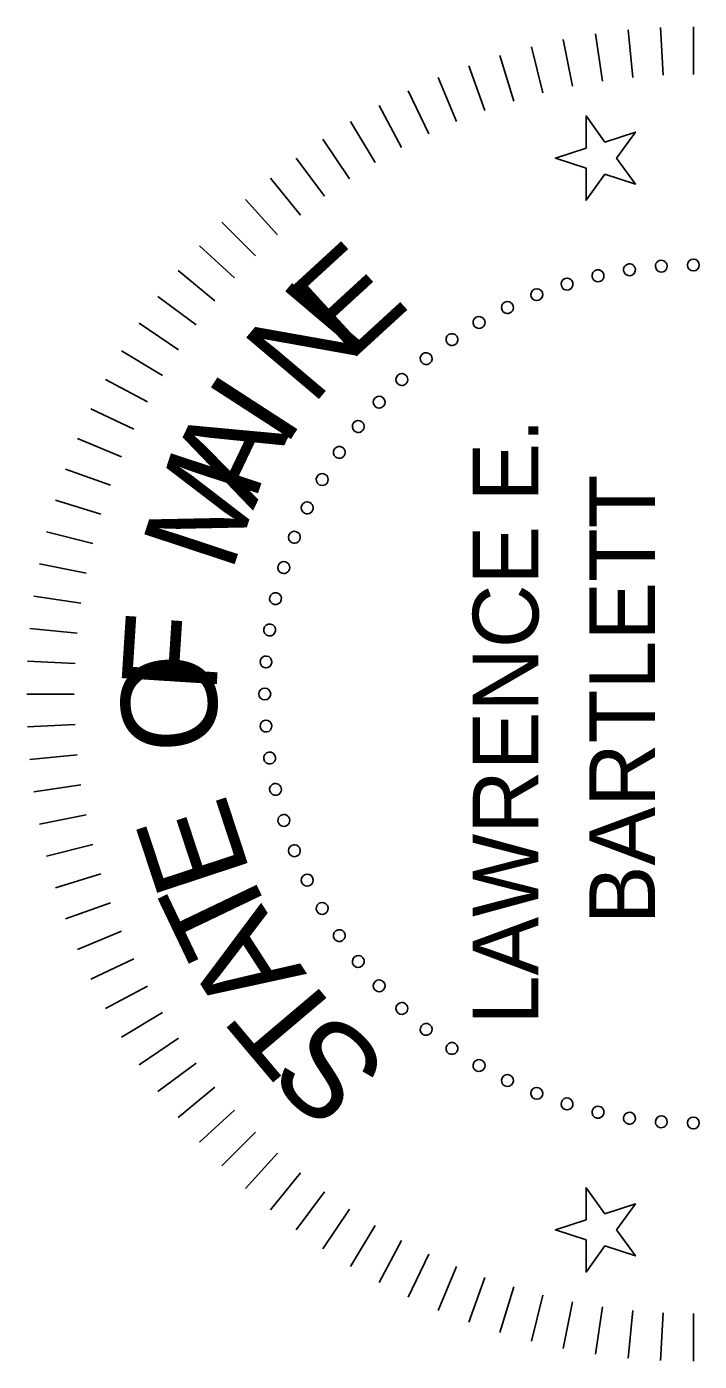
# Model space of a CAD drawing. Extents: x 9916 to 916479, y 6678 to 329942.
# Drawn here: x 916414.06 to 916434.15, y 329765.72 to 329805.54 of the extents above; entities that cross this region are included whole.
import ezdxf

# ---------------------------------------------------------------- set-up
doc = ezdxf.new("R2010")
doc.units = 0
doc.layers.add('Border', color=7, linetype='Continuous')
doc.layers.add('Default', color=7, linetype='Continuous')

# ---------------------------------------------------------------- blocks, each defined once
blk = doc.blocks.new('STAMP')
at = {"layer": 'Default'}
for p, q in [((-0.0007807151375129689, 0.009426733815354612), (-0.0007249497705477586, 0.00886053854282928)), ((-0.00039082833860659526, 0.009455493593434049), (-0.00036291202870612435, 0.008887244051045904)), ((-4.996003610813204e-18, 0.009465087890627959), (-4.996003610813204e-18, 0.008896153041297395)), ((0.0003908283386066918, 0.009455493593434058), (0.0003629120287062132, 0.008887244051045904)), ((0.0007807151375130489, 0.009426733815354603), (0.0007249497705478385, 0.00886053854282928)), ((-0.0015539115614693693, 0.009312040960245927), (-0.0014429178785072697, 0.00875403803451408)), ((-0.0011687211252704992, 0.009378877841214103), (-0.0010852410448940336, 0.008816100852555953)), ((0.0011687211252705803, 0.009378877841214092), (0.0010852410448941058, 0.008816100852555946)), ((0.001553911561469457, 0.009312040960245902), (0.001442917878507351, 0.008754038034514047)), ((-0.002312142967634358, 0.009122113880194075), (-0.002146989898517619, 0.008577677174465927)), ((-0.0019353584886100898, 0.009226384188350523), (-0.0017971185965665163, 0.008674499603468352)), ((0.0019353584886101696, 0.009226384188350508), (0.0017971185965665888, 0.008674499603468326)), ((0.0023121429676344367, 0.00912211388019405), (0.0021469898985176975, 0.008577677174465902)), ((-0.0026833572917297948, 0.008999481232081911), (-0.0024916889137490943, 0.00846380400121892)), ((0.002683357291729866, 0.008999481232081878), (0.0024916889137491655, 0.008463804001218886)), ((-0.003048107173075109, 0.008858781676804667), (-0.0028303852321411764, 0.008333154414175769)), ((0.00304810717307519, 0.008858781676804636), (0.002830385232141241, 0.008333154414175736)), ((-0.003405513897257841, 0.008700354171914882), (-0.0031622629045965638, 0.008186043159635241)), ((0.0034055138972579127, 0.008700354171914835), (0.0031622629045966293, 0.008186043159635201)), ((-0.0037547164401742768, 0.008524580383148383), (-0.0034865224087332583, 0.00802282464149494)), ((0.003754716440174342, 0.008524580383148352), (0.0034865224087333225, 0.008022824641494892)), ((-0.004094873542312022, 0.008331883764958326), (-0.003802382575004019, 0.0078438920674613)), ((0.0040948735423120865, 0.008331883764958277), (0.0038023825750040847, 0.007843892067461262)), ((-0.004425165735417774, 0.008122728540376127), (-0.004109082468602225, 0.0076496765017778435)), ((0.004425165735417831, 0.008122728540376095), (0.004109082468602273, 0.007649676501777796)), ((-0.004744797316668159, 0.007897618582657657), (-0.004405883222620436, 0.007440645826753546)), ((0.004744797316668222, 0.007897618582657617), (0.004405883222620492, 0.007440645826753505)), ((-0.0050529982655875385, 0.0076570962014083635), (-0.004692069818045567, 0.007217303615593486)), ((0.005052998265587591, 0.0076570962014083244), (0.004692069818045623, 0.0072173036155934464)), ((-0.005349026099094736, 0.007401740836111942), (-0.004966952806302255, 0.006980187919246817)), ((0.0053490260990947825, 0.0074017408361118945), (0.004966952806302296, 0.00698018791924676)), ((-0.0056321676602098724, 0.00713216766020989), (-0.00522986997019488, 0.006729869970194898)), ((0.005632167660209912, 0.007132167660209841), (0.005229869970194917, 0.006729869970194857)), ((-0.005901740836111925, 0.006849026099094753), (-0.005480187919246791, 0.006466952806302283)), ((0.005901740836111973, 0.0068490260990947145), (0.00548018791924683, 0.006466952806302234)), ((-0.006157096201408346, 0.006552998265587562), (-0.005717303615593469, 0.006192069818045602)), ((0.006157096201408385, 0.006552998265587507), (0.005717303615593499, 0.006192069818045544)), ((-0.00639761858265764, 0.006244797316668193), (-0.0059406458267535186, 0.0059058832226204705)), ((0.006397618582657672, 0.006244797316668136), (0.00594064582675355, 0.005905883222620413)), ((-0.006622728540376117, 0.0059251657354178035), (-0.006149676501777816, 0.005609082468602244)), ((0.006622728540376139, 0.005925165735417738), (0.006149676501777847, 0.005609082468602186)), ((-0.006831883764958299, 0.005594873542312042), (-0.0063438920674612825, 0.0053023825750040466)), ((0.006831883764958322, 0.005594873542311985), (0.006343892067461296, 0.005302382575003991)), ((-0.007024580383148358, 0.005254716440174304), (-0.006522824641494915, 0.004986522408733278)), ((0.007024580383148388, 0.005254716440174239), (0.006522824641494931, 0.004986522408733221)), ((-0.007200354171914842, 0.00490551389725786), (-0.006686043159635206, 0.004662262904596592)), ((0.00720035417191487, 0.004905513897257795), (0.00668604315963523, 0.004662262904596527)), ((-0.0073587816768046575, 0.004548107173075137), (-0.006833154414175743, 0.004330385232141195)), ((0.0073587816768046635, 0.0045481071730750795), (0.006833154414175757, 0.0043303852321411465)), ((-0.007499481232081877, 0.004183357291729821), (-0.006963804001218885, 0.003991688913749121)), ((0.0074994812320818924, 0.004183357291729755), (0.006963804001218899, 0.003991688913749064)), ((-0.007622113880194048, 0.0038121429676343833), (-0.007077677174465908, 0.003646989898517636)), ((0.007622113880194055, 0.003812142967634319), (0.007077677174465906, 0.00364698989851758)), ((-0.007726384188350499, 0.0034353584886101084), (-0.007174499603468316, 0.003297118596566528)), ((0.0077263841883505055, 0.0034353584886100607), (0.007174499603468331, 0.003297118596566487)), ((-0.0078120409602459, 0.0030539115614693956), (-0.007254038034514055, 0.0029429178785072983)), ((-0.006396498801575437, 0.0031478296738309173), (-0.006515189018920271, 0.0027825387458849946)), ((-0.006277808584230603, 0.0027825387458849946), (-0.006396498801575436, 0.0031478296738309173)), ((0.006277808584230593, 0.0027825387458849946), (0.006396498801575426, 0.0031478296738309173)), ((0.006396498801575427, 0.0031478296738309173), (0.0065151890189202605, 0.0027825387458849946)), ((0.007812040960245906, 0.003053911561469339), (0.007254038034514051, 0.0029429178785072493)), ((-0.006515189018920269, 0.0027825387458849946), (-0.006899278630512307, 0.0027825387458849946)), ((-0.006899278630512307, 0.0027825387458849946), (-0.006588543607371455, 0.002556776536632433)), ((-0.005893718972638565, 0.0027825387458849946), (-0.006277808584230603, 0.0027825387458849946)), ((-0.006204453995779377, 0.002556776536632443), (-0.005893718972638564, 0.0027825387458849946)), ((0.0062044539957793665, 0.002556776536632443), (0.005893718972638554, 0.0027825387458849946)), ((0.005893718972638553, 0.0027825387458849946), (0.00627780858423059, 0.0027825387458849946)), ((0.00651518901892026, 0.0027825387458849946), (0.006899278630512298, 0.0027825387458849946)), ((0.006899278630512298, 0.0027825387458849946), (0.006588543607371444, 0.002556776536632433)), ((-0.007878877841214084, 0.002668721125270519), (-0.007316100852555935, 0.0025852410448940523)), ((-0.006588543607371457, 0.002556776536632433), (-0.00670723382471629, 0.0021914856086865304)), ((-0.006085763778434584, 0.0021914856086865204), (-0.006204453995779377, 0.002556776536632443)), ((0.006085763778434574, 0.0021914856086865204), (0.006204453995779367, 0.002556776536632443)), ((0.006588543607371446, 0.002556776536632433), (0.0067072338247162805, 0.0021914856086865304)), ((0.007878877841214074, 0.0026687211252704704), (0.007316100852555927, 0.0025852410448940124)), ((-0.006707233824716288, 0.0021914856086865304), (-0.006396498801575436, 0.0024172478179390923)), ((-0.006396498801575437, 0.0024172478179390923), (-0.006085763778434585, 0.0021914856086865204)), ((0.006396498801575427, 0.0024172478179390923), (0.006085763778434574, 0.0021914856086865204)), ((0.006707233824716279, 0.0021914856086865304), (0.006396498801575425, 0.0024172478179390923)), ((-0.007926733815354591, 0.00228071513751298), (-0.007360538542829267, 0.0022249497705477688)), ((0.007926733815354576, 0.0022807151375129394), (0.007360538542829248, 0.002224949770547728)), ((-0.007955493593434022, 0.0018908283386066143), (-0.007387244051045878, 0.0018629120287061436)), ((0.007955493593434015, 0.0018908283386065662), (0.007387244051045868, 0.001862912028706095)), ((-0.007965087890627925, 0.0015000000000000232), (-0.0073961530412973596, 0.0015000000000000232)), ((0.007965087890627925, 0.0014999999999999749), (0.0073961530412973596, 0.0014999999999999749))]:
    blk.add_line(p, q, dxfattribs=at)
for points in [[(-0.006277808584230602, 0.0027825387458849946), (-0.006396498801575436, 0.0031478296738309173), (-0.006515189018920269, 0.0027825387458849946), (-0.006899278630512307, 0.0027825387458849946), (-0.006588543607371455, 0.002556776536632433), (-0.006707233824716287, 0.0021914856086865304), (-0.006396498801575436, 0.0024172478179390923), (-0.0060857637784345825, 0.0021914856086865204), (-0.006204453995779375, 0.002556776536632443), (-0.005893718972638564, 0.0027825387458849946)], [(0.006277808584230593, 0.0027825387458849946), (0.006396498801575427, 0.0031478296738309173), (0.00651518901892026, 0.0027825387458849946), (0.006899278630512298, 0.0027825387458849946), (0.006588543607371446, 0.002556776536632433), (0.006707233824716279, 0.0021914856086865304), (0.006396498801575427, 0.0024172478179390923), (0.006085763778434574, 0.0021914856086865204), (0.0062044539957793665, 0.002556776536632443), (0.005893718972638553, 0.0027825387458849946)]]:
    blk.add_lwpolyline(points, close=True, dxfattribs=at)
for centre, radius, start, end in [((-4.718447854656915e-18, 0.006620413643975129), 7.111685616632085e-05, 0, 180), ((-0.001139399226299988, 0.006492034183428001), 7.111685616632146e-05, 12.857142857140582, 192.8571428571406), ((-0.0007631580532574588, 0.006563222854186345), 7.111685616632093e-05, 8.571428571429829, 188.57142857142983), ((-0.0007631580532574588, 0.006563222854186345), 7.111685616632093e-05, 188.57142857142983, 8.571428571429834), ((-0.0003826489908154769, 0.006606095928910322), 7.111685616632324e-05, 4.285714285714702, 184.2857142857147), ((-0.0003826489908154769, 0.006606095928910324), 7.111685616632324e-05, 184.28571428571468, 4.2857142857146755), ((-4.718447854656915e-18, 0.006620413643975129), 7.111685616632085e-05, 180, 0), ((0.0003826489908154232, 0.0066060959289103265), 7.111685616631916e-05, 175.71428571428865, 355.7142857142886), ((0.0003826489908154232, 0.0066060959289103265), 7.111685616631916e-05, 355.7142857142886, 175.71428571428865), ((0.0007631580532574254, 0.006563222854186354), 7.111685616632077e-05, 171.42857142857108, 351.4285714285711), ((0.0007631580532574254, 0.006563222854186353), 7.111685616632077e-05, 351.42857142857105, 171.42857142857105), ((0.0011393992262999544, 0.006492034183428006), 7.111685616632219e-05, 347.14285714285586, 167.1428571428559), ((-0.0015092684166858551, 0.006392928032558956), 7.111685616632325e-05, 17.142857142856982, 197.142857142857), ((-0.0015092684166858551, 0.006392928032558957), 7.111685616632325e-05, 197.14285714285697, 17.14285714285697), ((-0.001139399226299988, 0.006492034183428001), 7.111685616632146e-05, 192.85714285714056, 12.857142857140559), ((0.0011393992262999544, 0.006492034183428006), 7.111685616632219e-05, 167.1428571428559, 347.14285714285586), ((0.0015092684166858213, 0.006392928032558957), 7.111685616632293e-05, 162.85714285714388, 342.8571428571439), ((0.0015092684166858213, 0.006392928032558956), 7.111685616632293e-05, 342.85714285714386, 162.85714285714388), ((-0.0018706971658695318, 0.006266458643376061), 7.111685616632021e-05, 21.42857142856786, 201.42857142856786), ((-0.0018706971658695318, 0.006266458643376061), 7.111685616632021e-05, 201.42857142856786, 21.428571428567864), ((0.0018706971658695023, 0.006266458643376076), 7.111685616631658e-05, 158.571428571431, 338.571428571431), ((0.0018706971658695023, 0.006266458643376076), 7.111685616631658e-05, 338.571428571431, 158.571428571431), ((-0.0022216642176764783, 0.0061133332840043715), 7.111685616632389e-05, 25.714285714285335, 205.71428571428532), ((-0.0022216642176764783, 0.006113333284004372), 7.111685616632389e-05, 205.71428571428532, 25.714285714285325), ((0.002221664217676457, 0.006113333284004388), 7.11168561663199e-05, 154.2857142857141, 334.2857142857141), ((0.002221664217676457, 0.006113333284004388), 7.11168561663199e-05, 334.2857142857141, 154.2857142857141), ((-0.0025602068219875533, 0.005934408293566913), 7.111685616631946e-05, 30.000000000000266, 210.00000000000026), ((-0.0025602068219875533, 0.005934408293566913), 7.111685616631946e-05, 210.00000000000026, 30.000000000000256), ((0.002560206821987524, 0.005934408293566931), 7.11168561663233e-05, 150.00000000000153, 330.00000000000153), ((0.002560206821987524, 0.005934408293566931), 7.111685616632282e-05, 330.0000000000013, 150.0000000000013), ((-0.002884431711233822, 0.005730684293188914), 7.11168561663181e-05, 34.28571428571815, 214.28571428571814), ((-0.002884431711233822, 0.005730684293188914), 7.111685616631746e-05, 214.2857142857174, 34.285714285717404), ((0.0028844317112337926, 0.005730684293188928), 7.111685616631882e-05, 145.71428571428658, 325.7142857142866), ((0.0028844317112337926, 0.005730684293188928), 7.111685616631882e-05, 325.7142857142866, 145.71428571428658), ((-0.003192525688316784, 0.0055033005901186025), 7.11168561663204e-05, 38.57142857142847, 218.57142857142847), ((-0.003192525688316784, 0.0055033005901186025), 7.111685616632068e-05, 218.57142857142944, 38.571428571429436), ((0.0031925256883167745, 0.00550330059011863), 7.111685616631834e-05, 141.42857142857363, 321.4285714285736), ((0.0031925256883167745, 0.00550330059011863), 7.111685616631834e-05, 321.4285714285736, 141.42857142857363), ((-0.0034827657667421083, 0.005253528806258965), 7.111685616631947e-05, 42.857142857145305, 222.8571428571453), ((-0.0034827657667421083, 0.005253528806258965), 7.111685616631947e-05, 222.8571428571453, 42.857142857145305), ((0.003482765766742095, 0.005253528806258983), 7.111685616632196e-05, 137.1428571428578, 317.1428571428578), ((0.003482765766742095, 0.005253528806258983), 7.111685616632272e-05, 317.1428571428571, 137.14285714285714), ((-0.0037535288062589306, 0.004982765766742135), 7.11168561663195e-05, 47.142857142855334, 227.14285714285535), ((-0.0037535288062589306, 0.004982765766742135), 7.11168561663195e-05, 227.14285714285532, 47.14285714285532), ((0.0037535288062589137, 0.004982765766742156), 7.111685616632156e-05, 132.85714285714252, 312.85714285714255), ((0.0037535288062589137, 0.004982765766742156), 7.111685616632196e-05, 312.8571428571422, 132.8571428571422), ((-0.004003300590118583, 0.004692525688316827), 7.111685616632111e-05, 51.428571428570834, 231.42857142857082), ((-0.004003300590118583, 0.004692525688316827), 7.111685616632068e-05, 231.42857142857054, 51.428571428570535), ((0.004003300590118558, 0.004692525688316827), 7.111685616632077e-05, 128.57142857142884, 308.57142857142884), ((0.004003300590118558, 0.004692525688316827), 7.111685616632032e-05, 308.5714285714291, 128.5714285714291), ((-0.0042306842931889, 0.004384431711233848), 7.11168561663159e-05, 55.71428571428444, 235.71428571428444), ((-0.0042306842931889, 0.004384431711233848), 7.111685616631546e-05, 235.7142857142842, 55.71428571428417), ((0.004230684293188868, 0.0043844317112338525), 7.111685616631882e-05, 124.28571428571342, 304.2857142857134), ((0.004230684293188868, 0.0043844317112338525), 7.111685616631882e-05, 304.2857142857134, 124.28571428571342), ((-0.004434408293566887, 0.004060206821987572), 7.111685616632e-05, 59.99999999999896, 239.99999999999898), ((-0.004434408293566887, 0.004060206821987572), 7.111685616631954e-05, 239.99999999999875, 59.999999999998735), ((0.004434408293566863, 0.004060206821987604), 7.111685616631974e-05, 120.00000000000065, 300.0000000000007), ((0.004434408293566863, 0.004060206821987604), 7.111685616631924e-05, 300.00000000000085, 120.00000000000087), ((-0.004613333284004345, 0.003721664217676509), 7.111685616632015e-05, 64.28571428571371, 244.2857142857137), ((-0.004613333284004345, 0.003721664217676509), 7.111685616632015e-05, 244.2857142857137, 64.2857142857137), ((0.004613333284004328, 0.0037216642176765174), 7.11168561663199e-05, 115.7142857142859, 295.7142857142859), ((0.004613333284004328, 0.0037216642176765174), 7.11168561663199e-05, 295.7142857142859, 115.71428571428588), ((-0.004766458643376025, 0.0033706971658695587), 7.111685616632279e-05, 68.57142857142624, 248.57142857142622), ((-0.004766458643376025, 0.0033706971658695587), 7.111685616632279e-05, 248.57142857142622, 68.57142857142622), ((0.004766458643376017, 0.0033706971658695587), 7.111685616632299e-05, 111.42857142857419, 291.4285714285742), ((0.004766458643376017, 0.0033706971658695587), 7.111685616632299e-05, 291.4285714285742, 111.42857142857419), ((-0.004892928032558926, 0.003009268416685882), 7.11168561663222e-05, 72.8571428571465, 252.8571428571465), ((-0.004892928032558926, 0.003009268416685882), 7.11168561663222e-05, 252.8571428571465, 72.8571428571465), ((0.004892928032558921, 0.003009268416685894), 7.111685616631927e-05, 107.14285714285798, 287.14285714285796), ((0.004892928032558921, 0.003009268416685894), 7.111685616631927e-05, 287.14285714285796, 107.14285714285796), ((-0.00499203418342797, 0.0026393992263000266), 7.111685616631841e-05, 77.14285714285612, 257.1428571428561), ((-0.004992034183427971, 0.0026393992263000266), 7.111685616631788e-05, 257.142857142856, 77.142857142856), ((0.004992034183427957, 0.002639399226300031), 7.111685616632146e-05, 102.85714285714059, 282.8571428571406), ((0.004992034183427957, 0.002639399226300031), 7.111685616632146e-05, 282.85714285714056, 102.85714285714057), ((-0.005063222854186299, 0.0022631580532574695), 7.111685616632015e-05, 81.42857142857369, 261.4285714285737), ((-0.005063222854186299, 0.0022631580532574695), 7.111685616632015e-05, 261.4285714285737, 81.42857142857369), ((0.005063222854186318, 0.0022631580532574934), 7.111685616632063e-05, 98.57142857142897, 278.57142857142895), ((0.005063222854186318, 0.0022631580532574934), 7.111685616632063e-05, 278.57142857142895, 98.57142857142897), ((-0.005106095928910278, 0.0018826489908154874), 7.111685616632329e-05, 85.7142857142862, 265.71428571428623), ((-0.005106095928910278, 0.0018826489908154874), 7.1116856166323e-05, 265.7142857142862, 85.71428571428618), ((0.005106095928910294, 0.0018826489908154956), 7.111685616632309e-05, 94.2857142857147, 274.2857142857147), ((0.005106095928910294, 0.0018826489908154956), 7.111685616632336e-05, 274.2857142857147, 94.28571428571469), ((-0.0051204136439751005, 0.0015000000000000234), 7.111685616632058e-05, 90, 270), ((-0.0051204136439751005, 0.0015000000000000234), 7.111685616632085e-05, 270, 90), ((0.005120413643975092, 0.0015000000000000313), 7.111685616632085e-05, 90, 270), ((0.005120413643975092, 0.0015000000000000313), 7.111685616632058e-05, 270, 90)]:
    blk.add_arc(centre, radius, start, end, dxfattribs=at)
for s, height, rotation, p in [('O', 0.0011378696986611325, 3.653799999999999, (-0.0006627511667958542, 0.007158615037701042)), ('F', 0.0011378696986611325, 356.3462, (-7.4134925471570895e-06, 0.007201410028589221)), ('E', 0.0011378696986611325, 18.2692, (-0.0021355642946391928, 0.00678635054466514)), ('M', 0.001137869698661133, 341.7308, (0.0014314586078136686, 0.0070187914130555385)), ('T', 0.0011378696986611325, 25.576899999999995, (-0.0027590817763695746, 0.006486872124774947)), ('A', 0.0011378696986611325, 334.4231, (0.002184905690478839, 0.00676168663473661)), ('A', 0.0011378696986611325, 32.884600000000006, (-0.003341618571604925, 0.006114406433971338)), ('I', 0.0011378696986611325, 327.1154, (0.0029245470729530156, 0.00638406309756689)), ('T', 0.001137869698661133, 40.19230000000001, (-0.003928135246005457, 0.005629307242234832)), ('N', 0.001137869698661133, 319.8077, (0.003425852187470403, 0.0060536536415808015)), ('S', 0.001137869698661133, 47.49999999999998, (-0.004421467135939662, 0.00509611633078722)), ('E', 0.001137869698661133, 312.5, (0.0039441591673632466, 0.005617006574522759))]:
    blk.add_text(s, height=height, rotation=rotation, dxfattribs=at).set_placement(p)
for s, p in [('LAWRENCE E.', (-0.003944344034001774, 0.0033503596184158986)), ('BARTLETT', (-0.0027479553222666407, 0.001958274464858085))]:
    blk.add_text(s, height=0.0007851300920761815, dxfattribs=at).set_placement(p)

msp = doc.modelspace()

# ---------------------------------------------------------------- block references
at = {"layer": 'Border', "xscale": 2499.999999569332, "yscale": 2499.999999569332, "rotation": 90}
msp.add_blockref('STAMP', (916437.7218680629, 329785.62897801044), dxfattribs=at)

doc.saveas('drawing.dxf')
